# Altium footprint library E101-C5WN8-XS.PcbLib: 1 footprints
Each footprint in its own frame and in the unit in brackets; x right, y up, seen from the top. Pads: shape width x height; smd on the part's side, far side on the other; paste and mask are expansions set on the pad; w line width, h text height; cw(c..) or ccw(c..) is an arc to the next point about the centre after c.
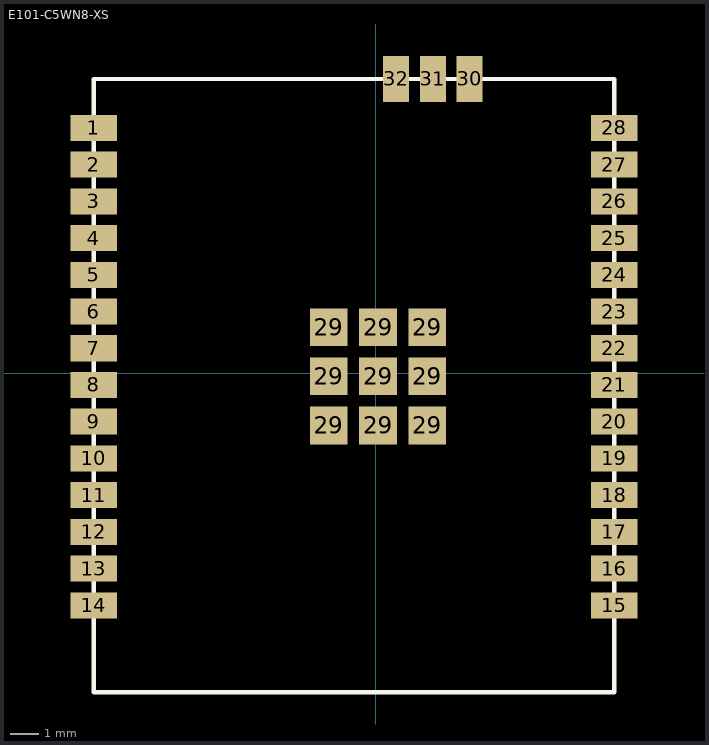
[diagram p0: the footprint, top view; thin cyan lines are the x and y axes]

## E101-C5WN8-XS [mm]
pads (40):
  rect 1.6x0.9 smd: 1(-9.75,8.49) 2(-9.75,7.22) 3(-9.75,5.95) 4(-9.75,4.68) 5(-9.75,3.41) 6(-9.75,2.14) 7(-9.75,0.87) 8(-9.75,-0.4) 9(-9.75,-1.67) 10(-9.75,-2.94) 11(-9.75,-4.21) 12(-9.75,-5.48) 13(-9.75,-6.75) 14(-9.75,-8.02) 15(8.25,-8.02) 16(8.25,-6.75) 17(8.25,-5.48) 18(8.25,-4.21) 19(8.25,-2.94) 20(8.25,-1.67) 21(8.25,-0.4) 22(8.25,0.87) 23(8.25,2.14) 24(8.25,3.41) 25(8.25,4.68) 26(8.25,5.95) 27(8.25,7.22) 28(8.25,8.49)
  rect 1.3x1.3 smd: 29(-1.62,-1.8) 29(-1.62,-0.1) 29(-1.62,1.6) 29(0.08,-1.8) 29(0.08,-0.1) 29(0.08,1.6) 29(1.78,-1.8) 29(1.78,-0.1) 29(1.78,1.6)
  rect 0.9x1.6 smd: 30(3.25,10.18) 31(1.98,10.18) 32(0.71,10.18)
Top Overlay:
  lines w0.15: -9.75,-11.02 8.25,-11.02 8.25,-8.65 8.25,10.18 3.811,10.18 -9.75,10.18 -9.75,-8.671 -9.75,-11.02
